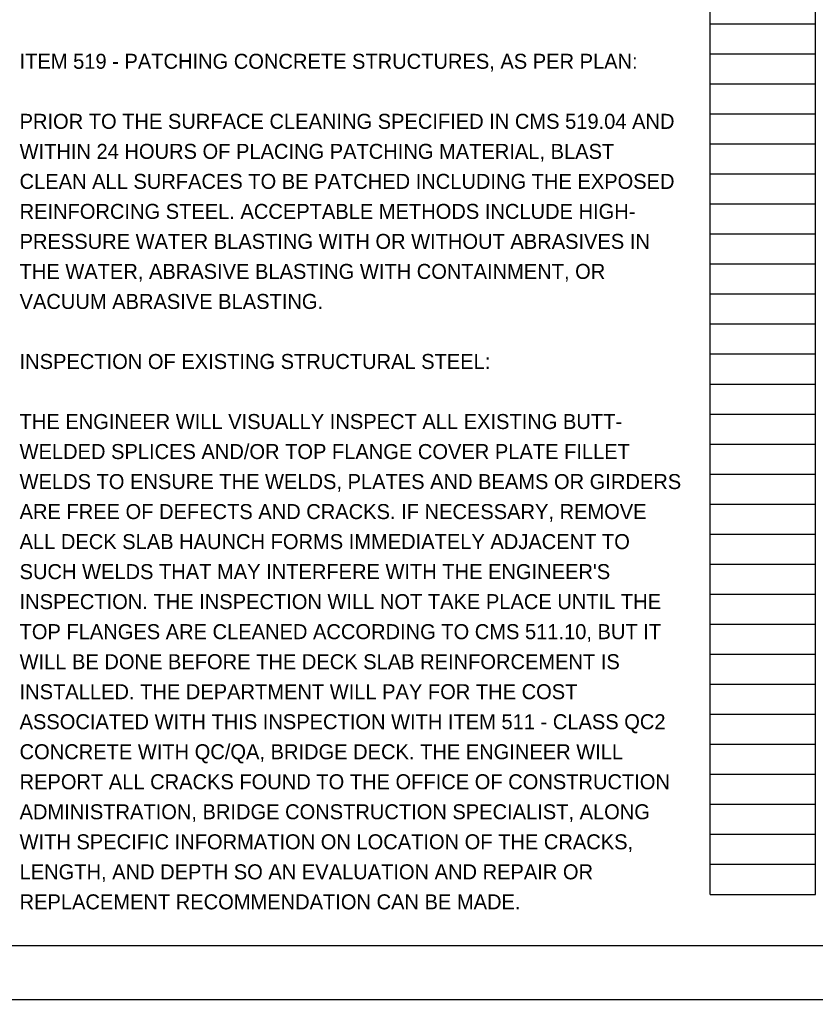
# Model space of a CAD drawing. Extents: x 0 to 34, y 0 to 22.
# Drawn here: x 17.24 to 24.66, y 0 to 9.14 of the extents above; entities that cross this region are included whole.
import ezdxf

# ---------------------------------------------------------------- set-up
doc = ezdxf.new("R2010")
doc.units = 0
for name, color, linetype in [('BR_P_Gen_Text', 7, 'Continuous'), ('SH_Border', 7, 'Continuous'), ('SH_Cut_Line', 7, 'Continuous'), ('SH_Data', 7, 'Continuous')]:
    doc.layers.add(name, color=color, linetype=linetype)

msp = doc.modelspace()

# ---------------------------------------------------------------- linework, layer by layer
at = {"layer": 'SH_Border'}
msp.add_lwpolyline([(1.5, 21.5), (33.5, 21.5), (33.5, 0.5), (1.5, 0.5)], close=True, dxfattribs=at)
at = {"layer": 'SH_Cut_Line'}
msp.add_lwpolyline([(0, 0), (34, 0), (34, 22), (0, 22)], close=True, dxfattribs=at)
at = {"layer": 'SH_Data'}
for p, q in [((23.68, 0.98), (23.68, 21.14)), ((24.66, 0.98), (24.66, 21.14)), ((23.68, 9.1), (24.66, 9.1)), ((23.68, 8.82), (24.66, 8.82)), ((23.68, 8.54), (24.66, 8.54)), ((23.68, 8.26), (24.66, 8.26)), ((23.68, 7.98), (24.66, 7.98)), ((23.68, 7.7), (24.66, 7.7)), ((23.68, 7.42), (24.66, 7.42)), ((23.68, 7.14), (24.66, 7.14)), ((23.68, 6.86), (24.66, 6.86)), ((23.68, 6.58), (24.66, 6.58)), ((23.68, 6.3), (24.66, 6.3)), ((23.68, 6.02), (24.66, 6.02)), ((23.68, 5.74), (24.66, 5.74)), ((23.68, 5.46), (24.66, 5.46)), ((23.68, 5.18), (24.66, 5.18)), ((23.68, 4.9), (24.66, 4.9)), ((23.68, 4.62), (24.66, 4.62)), ((23.68, 4.34), (24.66, 4.34)), ((23.68, 4.06), (24.66, 4.06)), ((23.68, 3.78), (24.66, 3.78)), ((23.68, 3.5), (24.66, 3.5)), ((23.68, 3.22), (24.66, 3.22)), ((23.68, 2.94), (24.66, 2.94)), ((23.68, 2.66), (24.66, 2.66)), ((23.68, 2.38), (24.66, 2.38)), ((23.68, 2.1), (24.66, 2.1)), ((23.68, 1.82), (24.66, 1.82)), ((23.68, 1.54), (24.66, 1.54)), ((23.68, 1.26), (24.66, 1.26)), ((23.68, 0.98), (24.66, 0.98))]:
    msp.add_line(p, q, dxfattribs=at)

# ---------------------------------------------------------------- texts
at = {"layer": 'BR_P_Gen_Text'}
for s, p in [('ITEM 519 - PATCHING CONCRETE STRUCTURES, AS PER PLAN:', (17.24, 8.68)), ('PRIOR TO THE SURFACE CLEANING SPECIFIED IN CMS 519.04 AND ', (17.24, 8.12)), ('WITHIN 24 HOURS OF PLACING PATCHING MATERIAL, BLAST ', (17.24, 7.84)), ('CLEAN ALL SURFACES TO BE PATCHED INCLUDING THE EXPOSED ', (17.24, 7.56)), ('REINFORCING STEEL. ACCEPTABLE METHODS INCLUDE HIGH-', (17.24, 7.28)), ('PRESSURE WATER BLASTING WITH OR WITHOUT ABRASIVES IN ', (17.24, 7)), ('THE WATER, ABRASIVE BLASTING WITH CONTAINMENT, OR ', (17.24, 6.72)), ('VACUUM ABRASIVE BLASTING.', (17.24, 6.44)), ('INSPECTION OF EXISTING STRUCTURAL STEEL:', (17.24, 5.88)), ('THE ENGINEER WILL VISUALLY INSPECT ALL EXISTING BUTT-', (17.24, 5.32)), ('WELDED SPLICES AND/OR TOP FLANGE COVER PLATE FILLET ', (17.24, 5.04)), ('WELDS TO ENSURE THE WELDS, PLATES AND BEAMS OR GIRDERS ', (17.24, 4.76)), ('ARE FREE OF DEFECTS AND CRACKS. IF NECESSARY, REMOVE ', (17.24, 4.48)), ('ALL DECK SLAB HAUNCH FORMS IMMEDIATELY ADJACENT TO ', (17.24, 4.2)), ("SUCH WELDS THAT MAY INTERFERE WITH THE ENGINEER'S ", (17.24, 3.92)), ('INSPECTION. THE INSPECTION WILL NOT TAKE PLACE UNTIL THE ', (17.24, 3.64)), ('TOP FLANGES ARE CLEANED ACCORDING TO CMS 511.10, BUT IT ', (17.24, 3.36)), ('WILL BE DONE BEFORE THE DECK SLAB REINFORCEMENT IS ', (17.24, 3.08)), ('INSTALLED. THE DEPARTMENT WILL PAY FOR THE COST ', (17.24, 2.8)), ('ASSOCIATED WITH THIS INSPECTION WITH ITEM 511 - CLASS QC2 ', (17.24, 2.52)), ('CONCRETE WITH QC/QA, BRIDGE DECK. THE ENGINEER WILL ', (17.24, 2.24)), ('REPORT ALL CRACKS FOUND TO THE OFFICE OF CONSTRUCTION ', (17.24, 1.96)), ('ADMINISTRATION, BRIDGE CONSTRUCTION SPECIALIST, ALONG ', (17.24, 1.68)), ('WITH SPECIFIC INFORMATION ON LOCATION OF THE CRACKS, ', (17.24, 1.4)), ('LENGTH, AND DEPTH SO AN EVALUATION AND REPAIR OR ', (17.24, 1.12)), ('REPLACEMENT RECOMMENDATION CAN BE MADE.', (17.24, 0.84))]:
    msp.add_text(s, height=0.14, dxfattribs=at).set_placement(p)

doc.saveas('drawing.dxf')
